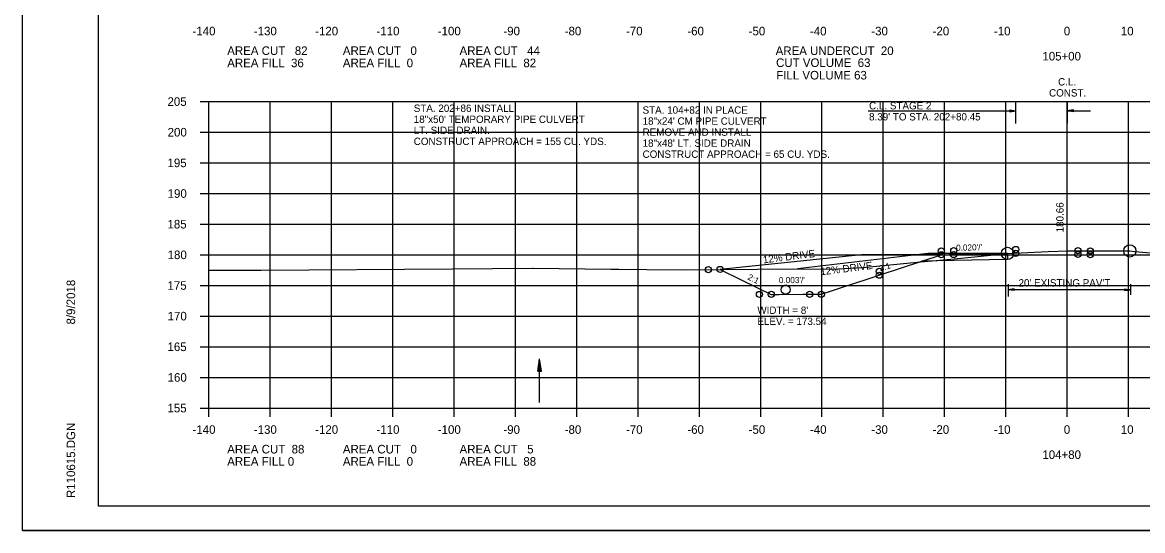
# Model space of a CAD drawing. Extents: x 1372132 to 1372465, y 380083 to 381790.
# Drawn here: x 1372131.6 to 1372314.3, y 380296.8 to 380379.7 of the extents above; entities that cross this region are included whole.
import ezdxf

# ---------------------------------------------------------------- set-up
doc = ezdxf.new("R2010")
doc.units = 0
for name, color, linetype in [('Default', 7, 'Continuous'), ('R_Alt Surface', 7, 'Continuous'), ('R_Axis', 7, 'Continuous'), ('R_Axis Annot', 7, 'Continuous'), ('R_Border', 7, 'Continuous'), ('R_Dimension', 7, 'Continuous'), ('R_Draft', 7, 'Continuous'), ('R_Exist Surface', 7, 'Continuous'), ('R_Fin Surface', 7, 'Continuous'), ('R_Grid', 7, 'Continuous'), ('R_No Plot', 7, 'Continuous'), ('R_Xsect Elev', 7, 'Continuous'), ('R_Xsect Slope', 7, 'Continuous')]:
    doc.layers.add(name, color=color, linetype=linetype)

msp = doc.modelspace()

# ---------------------------------------------------------------- linework, layer by layer
at = {"layer": 'Default'}
for p, q in [((1372279.26, 380342.05), (1372258.02, 380339.5)), ((1372292.26, 380342.05), (1372279.26, 380342.05)), ((1372268.47, 380341.82), (1372245.4, 380339.42)), ((1372281.47, 380341.82), (1372268.47, 380341.82))]:
    msp.add_line(p, q, dxfattribs=at)
msp.add_circle((1372256.09, 380336.14), 0.75, dxfattribs=at)
at = {"layer": 'R_Alt Surface'}
msp.add_lwpolyline([(1372292.26, 380341.03), (1372283.5, 380340.86), (1372278.24, 380340.76)], dxfattribs=at)
at = {"layer": 'R_Axis'}
for p, q in [((1372160.61, 380366.81), (1372162.01, 380366.81)), ((1372162.01, 380316.81), (1372162.01, 380366.81)), ((1372160.61, 380361.81), (1372162.01, 380361.81)), ((1372160.61, 380356.81), (1372162.01, 380356.81)), ((1372160.61, 380351.81), (1372162.01, 380351.81)), ((1372160.61, 380346.81), (1372162.01, 380346.81)), ((1372160.61, 380341.81), (1372162.01, 380341.81)), ((1372160.61, 380336.81), (1372162.01, 380336.81)), ((1372160.61, 380331.81), (1372162.01, 380331.81)), ((1372160.61, 380326.81), (1372162.01, 380326.81)), ((1372160.61, 380321.81), (1372162.01, 380321.81)), ((1372160.61, 380316.81), (1372162.01, 380316.81)), ((1372162.01, 380316.81), (1372442.01, 380316.81)), ((1372162.01, 380315.41), (1372162.01, 380316.81)), ((1372172.01, 380315.41), (1372172.01, 380316.81)), ((1372182.01, 380315.41), (1372182.01, 380316.81)), ((1372192.01, 380315.41), (1372192.01, 380316.81)), ((1372202.01, 380315.41), (1372202.01, 380316.81)), ((1372212.01, 380315.41), (1372212.01, 380316.81)), ((1372222.01, 380315.41), (1372222.01, 380316.81)), ((1372232.01, 380315.41), (1372232.01, 380316.81)), ((1372242.01, 380315.41), (1372242.01, 380316.81)), ((1372252.01, 380315.41), (1372252.01, 380316.81)), ((1372262.01, 380315.41), (1372262.01, 380316.81)), ((1372272.01, 380315.41), (1372272.01, 380316.81)), ((1372282.01, 380315.41), (1372282.01, 380316.81)), ((1372292.01, 380315.41), (1372292.01, 380316.81)), ((1372302.01, 380315.41), (1372302.01, 380316.81)), ((1372312.01, 380315.41), (1372312.01, 380316.81))]:
    msp.add_line(p, q, dxfattribs=at)
at = {"layer": 'R_Border'}
for p, q in [((1372144.01, 380300.81), (1372144.01, 380506.27)), ((1372144.01, 380300.81), (1372144.01, 380300.81)), ((1372460.19, 380300.81), (1372144.01, 380300.81))]:
    msp.add_line(p, q, dxfattribs=at)
at = {"layer": 'R_Dimension'}
for p, q in [((1372215.66, 380322.86), (1372215.96, 380324.86)), ((1372215.66, 380322.86), (1372215.96, 380324.86)), ((1372215.71, 380322.86), (1372215.96, 380324.53)), ((1372215.71, 380322.86), (1372215.96, 380324.53)), ((1372215.76, 380322.86), (1372215.96, 380324.18)), ((1372215.76, 380322.86), (1372215.96, 380324.18)), ((1372215.81, 380322.86), (1372215.96, 380323.85)), ((1372215.81, 380322.86), (1372215.96, 380323.85)), ((1372216.26, 380322.86), (1372215.96, 380324.86)), ((1372216.26, 380322.86), (1372215.96, 380324.86)), ((1372216.21, 380322.86), (1372215.96, 380324.53)), ((1372216.21, 380322.86), (1372215.96, 380324.53)), ((1372216.16, 380322.86), (1372215.96, 380324.18)), ((1372216.16, 380322.86), (1372215.96, 380324.18)), ((1372216.11, 380322.86), (1372215.96, 380323.85)), ((1372216.11, 380322.86), (1372215.96, 380323.85)), ((1372215.66, 380322.86), (1372216.26, 380322.86)), ((1372215.66, 380322.86), (1372216.26, 380322.86)), ((1372215.86, 380322.86), (1372215.96, 380323.51)), ((1372215.86, 380322.86), (1372215.96, 380323.51)), ((1372215.91, 380322.86), (1372215.96, 380323.18)), ((1372215.91, 380322.86), (1372215.96, 380323.18)), ((1372216.06, 380322.86), (1372215.96, 380323.51)), ((1372216.06, 380322.86), (1372215.96, 380323.51)), ((1372216.01, 380322.86), (1372215.96, 380323.18)), ((1372216.01, 380322.86), (1372215.96, 380323.18))]:
    msp.add_line(p, q, dxfattribs=at)
at = {"layer": 'R_Draft'}
for p, q in [((1372293.62, 380363.22), (1372293.62, 380366.81)), ((1372302.01, 380366.81), (1372302.01, 380363.22)), ((1372269.52, 380365.3), (1372293.62, 380365.3)), ((1372292.62, 380365.45), (1372293.62, 380365.3)), ((1372292.62, 380365.45), (1372292.62, 380365.15)), ((1372292.62, 380365.45), (1372293.62, 380365.3)), ((1372292.62, 380365.45), (1372292.62, 380365.15)), ((1372292.62, 380365.42), (1372293.45, 380365.3)), ((1372292.62, 380365.42), (1372293.45, 380365.3)), ((1372292.62, 380365.4), (1372293.28, 380365.3)), ((1372292.62, 380365.4), (1372293.28, 380365.3)), ((1372292.62, 380365.37), (1372293.11, 380365.3)), ((1372292.62, 380365.37), (1372293.11, 380365.3)), ((1372292.62, 380365.35), (1372292.94, 380365.3)), ((1372292.62, 380365.35), (1372292.94, 380365.3)), ((1372292.62, 380365.32), (1372292.78, 380365.3)), ((1372292.62, 380365.32), (1372292.78, 380365.3)), ((1372292.62, 380365.15), (1372293.62, 380365.3)), ((1372292.62, 380365.25), (1372292.94, 380365.3)), ((1372292.62, 380365.2), (1372293.28, 380365.3)), ((1372292.62, 380365.17), (1372293.45, 380365.3)), ((1372292.62, 380365.23), (1372293.11, 380365.3)), ((1372292.62, 380365.28), (1372292.78, 380365.3)), ((1372292.62, 380365.15), (1372293.62, 380365.3)), ((1372292.62, 380365.25), (1372292.94, 380365.3)), ((1372292.62, 380365.2), (1372293.28, 380365.3)), ((1372292.62, 380365.17), (1372293.45, 380365.3)), ((1372292.62, 380365.23), (1372293.11, 380365.3)), ((1372292.62, 380365.28), (1372292.78, 380365.3)), ((1372303.01, 380365.45), (1372302.01, 380365.3)), ((1372302.01, 380365.3), (1372305.82, 380365.3)), ((1372303.01, 380365.15), (1372302.01, 380365.3)), ((1372303.01, 380365.42), (1372302.18, 380365.3)), ((1372303.01, 380365.17), (1372302.18, 380365.3)), ((1372303.01, 380365.4), (1372302.35, 380365.3)), ((1372303.01, 380365.2), (1372302.35, 380365.3)), ((1372303.01, 380365.37), (1372302.52, 380365.3)), ((1372303.01, 380365.23), (1372302.52, 380365.3)), ((1372303.01, 380365.35), (1372302.69, 380365.3)), ((1372303.01, 380365.25), (1372302.69, 380365.3)), ((1372303.01, 380365.32), (1372302.86, 380365.3)), ((1372303.01, 380365.28), (1372302.86, 380365.3)), ((1372303.01, 380365.15), (1372303.01, 380365.45)), ((1372292.26, 380342.03), (1372292.26, 380341.03)), ((1372292.36, 380337.04), (1372292.36, 380335.03)), ((1372312.34, 380337.04), (1372312.34, 380335.27)), ((1372293.36, 380336.27), (1372292.36, 380336.12)), ((1372293.36, 380336.27), (1372292.36, 380336.12)), ((1372312.34, 380336.12), (1372292.36, 380336.12)), ((1372293.36, 380335.97), (1372292.36, 380336.12)), ((1372293.36, 380335.97), (1372292.36, 380336.12)), ((1372292.36, 380335.27), (1372292.36, 380335.27)), ((1372293.36, 380336.25), (1372292.53, 380336.12)), ((1372293.36, 380336.25), (1372292.53, 380336.12)), ((1372293.36, 380336), (1372292.53, 380336.12)), ((1372293.36, 380336), (1372292.53, 380336.12)), ((1372293.36, 380336.22), (1372292.7, 380336.12)), ((1372293.36, 380336.22), (1372292.7, 380336.12)), ((1372293.36, 380336.02), (1372292.7, 380336.12)), ((1372293.36, 380336.02), (1372292.7, 380336.12)), ((1372293.36, 380336.2), (1372292.86, 380336.12)), ((1372293.36, 380336.2), (1372292.86, 380336.12)), ((1372293.36, 380336.05), (1372292.86, 380336.12)), ((1372293.36, 380336.05), (1372292.86, 380336.12)), ((1372293.36, 380336.17), (1372293.03, 380336.12)), ((1372293.36, 380336.17), (1372293.03, 380336.12)), ((1372293.36, 380336.08), (1372293.03, 380336.12)), ((1372293.36, 380336.08), (1372293.03, 380336.12)), ((1372293.36, 380336.15), (1372293.2, 380336.12)), ((1372293.36, 380336.15), (1372293.2, 380336.12)), ((1372293.36, 380336.1), (1372293.2, 380336.12)), ((1372293.36, 380336.1), (1372293.2, 380336.12)), ((1372293.36, 380335.97), (1372293.36, 380336.27)), ((1372293.36, 380335.97), (1372293.36, 380336.27)), ((1372311.34, 380336.27), (1372312.34, 380336.12)), ((1372311.34, 380336.27), (1372311.34, 380335.97)), ((1372311.34, 380336.25), (1372312.17, 380336.12)), ((1372311.34, 380336.22), (1372312, 380336.12)), ((1372311.34, 380336.2), (1372311.83, 380336.12)), ((1372311.34, 380336.17), (1372311.66, 380336.12)), ((1372311.34, 380336.15), (1372311.5, 380336.12)), ((1372311.34, 380335.97), (1372312.34, 380336.12)), ((1372311.34, 380336.08), (1372311.66, 380336.12)), ((1372311.34, 380336.02), (1372312, 380336.12)), ((1372311.34, 380336), (1372312.17, 380336.12)), ((1372311.34, 380336.05), (1372311.83, 380336.12)), ((1372311.34, 380336.1), (1372311.5, 380336.12)), ((1372215.96, 380317.72), (1372215.96, 380324.86))]:
    msp.add_line(p, q, dxfattribs=at)
at = {"layer": 'R_Exist Surface'}
msp.add_lwpolyline([(1372162.01, 380339.29), (1372170.49, 380339.29), (1372201.73, 380339.51), (1372214.81, 380339.61), (1372214.93, 380339.61), (1372227.59, 380339.47), (1372228.86, 380339.46), (1372233.42, 380339.42), (1372239.31, 380339.37), (1372257.6, 380339.5), (1372263.62, 380339.46), (1372268.66, 380339.77), (1372278.08, 380340.69), (1372280.61, 380340.89), (1372284.7, 380341.28), (1372292.26, 380342.05), (1372298.87, 380342.34), (1372302.12, 380342.48), (1372310.73, 380342.44), (1372312.22, 380342.44), (1372313.04, 380342.36), (1372317.49, 380341.96)], dxfattribs=at)
at = {"layer": 'R_Fin Surface'}
msp.add_lwpolyline([(1372245.4, 380339.42), (1372248.95, 380337.69), (1372253.73, 380335.36), (1372255.05, 380335.36), (1372258.89, 380335.37), (1372260.15, 380335.37), (1372261.9, 380335.38), (1372263.72, 380335.98), (1372264.88, 380336.36), (1372269.72, 380337.95), (1372271.35, 380338.49), (1372274.99, 380339.69), (1372281.47, 380341.82), (1372282.76, 380341.85), (1372283.5, 380341.86), (1372292.26, 380342.03)], dxfattribs=at)
at = {"layer": 'R_Grid'}
for p, q in [((1372162.01, 380366.81), (1372442.01, 380366.81)), ((1372162.01, 380316.81), (1372162.01, 380366.81)), ((1372172.01, 380316.81), (1372172.01, 380366.81)), ((1372182.01, 380316.81), (1372182.01, 380366.81)), ((1372192.01, 380316.81), (1372192.01, 380366.81)), ((1372202.01, 380316.81), (1372202.01, 380366.81)), ((1372212.01, 380316.81), (1372212.01, 380366.81)), ((1372222.01, 380316.81), (1372222.01, 380366.81)), ((1372232.01, 380316.81), (1372232.01, 380366.81)), ((1372242.01, 380316.81), (1372242.01, 380366.81)), ((1372252.01, 380316.81), (1372252.01, 380366.81)), ((1372262.01, 380316.81), (1372262.01, 380366.81)), ((1372272.01, 380316.81), (1372272.01, 380366.81)), ((1372282.01, 380316.81), (1372282.01, 380366.81)), ((1372292.01, 380316.81), (1372292.01, 380366.81)), ((1372302.01, 380316.81), (1372302.01, 380366.81)), ((1372312.01, 380316.81), (1372312.01, 380366.81)), ((1372162.01, 380361.81), (1372442.01, 380361.81)), ((1372162.01, 380356.81), (1372442.01, 380356.81)), ((1372162.01, 380351.81), (1372442.01, 380351.81)), ((1372162.01, 380346.81), (1372442.01, 380346.81)), ((1372162.01, 380341.81), (1372442.01, 380341.81)), ((1372162.01, 380336.81), (1372442.01, 380336.81)), ((1372162.01, 380331.81), (1372442.01, 380331.81)), ((1372162.01, 380326.81), (1372442.01, 380326.81)), ((1372162.01, 380321.81), (1372442.01, 380321.81)), ((1372162.01, 380316.81), (1372442.01, 380316.81))]:
    msp.add_line(p, q, dxfattribs=at)
at = {"layer": 'R_No Plot'}
msp.add_line((1372131.61, 380296.83), (1372464.95, 380296.83), dxfattribs=at)
for points in [[(1372131.61, 380510.17), (1372464.95, 380510.17), (1372464.95, 380296.83), (1372131.61, 380296.83)], [(1372377.93, 380506.27), (1372377.93, 380496.39), (1372413.67, 380496.39), (1372413.67, 380493.47), (1372436.87, 380493.47), (1372436.87, 380469.14), (1372460.19, 380469.14), (1372460.19, 380300.81), (1372144.01, 380300.81), (1372144.01, 380506.27)]]:
    msp.add_lwpolyline(points, close=True, dxfattribs=at)
for centre, radius in [((1372281.47, 380342.45), 0.5), ((1372281.47, 380341.82), 0.5), ((1372283.5, 380342.49), 0.5), ((1372283.5, 380341.86), 0.5), ((1372292.26, 380342.05), 1), ((1372293.62, 380342.69), 0.5), ((1372293.62, 380342.06), 0.5), ((1372303.74, 380342.49), 0.5), ((1372303.74, 380341.87), 0.5), ((1372305.76, 380342.45), 0.5), ((1372305.76, 380341.83), 0.5), ((1372312.22, 380342.44), 1), ((1372243.49, 380339.4), 0.5), ((1372245.4, 380339.42), 0.5), ((1372271.35, 380339.11), 0.5), ((1372271.35, 380338.49), 0.5), ((1372251.81, 380335.35), 0.5), ((1372253.73, 380335.36), 0.5), ((1372259.98, 380335.37), 0.5), ((1372261.9, 380335.38), 0.5)]:
    msp.add_circle(centre, radius, dxfattribs=at)
at = {"layer": 'R_Xsect Elev'}
msp.add_line((1372302.01, 380342.47), (1372302.01, 380352.47), dxfattribs=at)

# ---------------------------------------------------------------- texts
at = {"layer": 'Default'}
for s, p in [('STA. 202+86 INSTALL ', (1372195.43, 380365.12)), ('18"x50\' TEMPORARY PIPE CULVERT', (1372195.43, 380363.32)), ('LT. SIDE DRAIN.', (1372195.43, 380361.52)), ('CONSTRUCT APPROACH = 155 CU. YDS.', (1372195.43, 380359.72))]:
    msp.add_text(s, height=1.2, dxfattribs=at).set_placement(p)
for rotation, p in [(7.1218, (1372252.45, 380340.4)), (7.1481, (1372261.81, 380338.45))]:
    msp.add_text('12% DRIVE', height=1.2, rotation=rotation, dxfattribs=at).set_placement(p)
at = {"layer": 'R_Axis Annot'}
for s, p in [('-140', (1372159.35, 380377.61)), ('-130', (1372169.35, 380377.61)), ('-120', (1372179.35, 380377.61)), ('-110', (1372189.35, 380377.61)), ('-100', (1372199.35, 380377.61)), ('-90', (1372210.05, 380377.61)), ('-80', (1372220.05, 380377.61)), ('-70', (1372230.05, 380377.61)), ('-60', (1372240.05, 380377.61)), ('-50', (1372250.05, 380377.61)), ('-40', (1372260.05, 380377.61)), ('-30', (1372270.05, 380377.61)), ('-20', (1372280.05, 380377.61)), ('-10', (1372290.05, 380377.61)), ('0', (1372301.45, 380377.61)), ('10', (1372310.75, 380377.61)), ('AREA CUT   82', (1372165.01, 380374.41)), ('AREA CUT   0', (1372183.87, 380374.41)), ('AREA CUT   44', (1372202.9, 380374.41)), ('AREA UNDERCUT  20', (1372254.45, 380374.4)), ('105+00', (1372297.95, 380373.51)), ('AREA FILL  36', (1372165.01, 380372.41)), ('AREA FILL  0', (1372183.87, 380372.41)), ('AREA FILL  82', (1372202.9, 380372.41)), ('CUT VOLUME  63', (1372254.52, 380372.45)), ('FILL VOLUME 63', (1372254.55, 380370.41)), ('205', (1372155.27, 380366.11)), ('200', (1372155.29, 380361.11)), ('195', (1372155.27, 380356.11)), ('190', (1372155.29, 380351.11)), ('185', (1372155.27, 380346.11)), ('180', (1372155.29, 380341.11)), ('175', (1372155.27, 380336.11)), ('170', (1372155.29, 380331.11)), ('165', (1372155.27, 380326.11)), ('160', (1372155.29, 380321.11)), ('155', (1372155.27, 380316.11)), ('-140', (1372159.35, 380312.61)), ('-130', (1372169.35, 380312.61)), ('-120', (1372179.35, 380312.61)), ('-110', (1372189.35, 380312.61)), ('-100', (1372199.35, 380312.61)), ('-90', (1372210.05, 380312.61)), ('-80', (1372220.05, 380312.61)), ('-70', (1372230.05, 380312.61)), ('-60', (1372240.05, 380312.61)), ('-50', (1372250.05, 380312.61)), ('-40', (1372260.05, 380312.61)), ('-30', (1372270.05, 380312.61)), ('-20', (1372280.05, 380312.61)), ('-10', (1372290.05, 380312.61)), ('0', (1372301.45, 380312.61)), ('10', (1372310.75, 380312.61)), ('AREA CUT  88', (1372165.01, 380309.41)), ('AREA CUT   0', (1372183.87, 380309.41)), ('AREA CUT   5', (1372202.9, 380309.41)), ('104+80', (1372297.95, 380308.51)), ('AREA FILL 0', (1372165.01, 380307.41)), ('AREA FILL  0', (1372183.87, 380307.41)), ('AREA FILL  88', (1372202.9, 380307.41))]:
    msp.add_text(s, height=1.4, dxfattribs=at).set_placement(p)
at = {"layer": 'R_Border'}
for s, p in [('8/9/2018', (1372140.21, 380330.45)), ('R110615.DGN', (1372140.21, 380302.14))]:
    msp.add_text(s, height=1.4, rotation=90, dxfattribs=at).set_placement(p)
at = {"layer": 'R_Dimension'}
for s, p in [('STA. 104+82 IN PLACE', (1372232.75, 380364.83)), ('18"x24\' CM PIPE CULVERT', (1372232.75, 380363.03)), ('REMOVE AND INSTALL', (1372232.75, 380361.23)), ('18"x48\' LT. SIDE DRAIN', (1372232.75, 380359.43)), ('CONSTRUCT APPROACH = 65 CU. YDS.', (1372232.75, 380357.63)), ("WIDTH = 8'", (1372251.47, 380332.17)), ('ELEV. = 173.54', (1372251.47, 380330.37))]:
    msp.add_text(s, height=1.2, dxfattribs=at).set_placement(p)
at = {"layer": 'R_Draft'}
for s, p in [('C.L. ', (1372300.51, 380369.43)), ('CONST. ', (1372299.04, 380367.63)), ('C.L. STAGE 2', (1372269.69, 380365.53)), ("8.39' TO STA. 202+80.45", (1372269.69, 380363.73)), ("20' EXISTING PAV'T", (1372294.06, 380336.64))]:
    msp.add_text(s, height=1.2, rotation=360, dxfattribs=at).set_placement(p)
at = {"layer": 'R_Xsect Elev'}
msp.add_text('180.66', height=1.2, rotation=90, dxfattribs=at).set_placement((1372301.41, 380345.47))
at = {"layer": 'R_Xsect Slope'}
for s, rotation, p in [("0.020'/'", 1.1323, (1372283.89, 380342.47)), ('3:1', 18.2224, (1372271.53, 380339.07)), ('2:1', 334.0424, (1372249.78, 380337.84)), ("0.003'/'", 0.1452, (1372254.98, 380337.19))]:
    msp.add_text(s, height=1, rotation=rotation, dxfattribs=at).set_placement(p)

doc.saveas('drawing.dxf')
